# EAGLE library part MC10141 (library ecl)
Four Bit Universal Shift Register
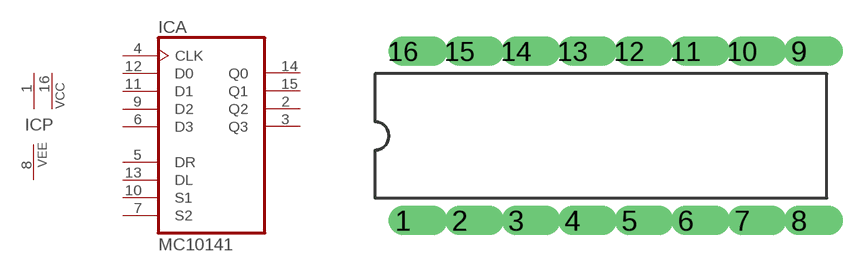
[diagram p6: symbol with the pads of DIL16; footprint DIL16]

Designator prefix IC; gates A=MC10141 P=2VCC1VEE

## MC10141  [DIL16]
1  P:VCC  pwr
2  A:Q2  out
3  A:Q3  out
4  A:CLK  in
5  A:DR  in
6  A:D3  in
7  A:S2  in
8  P:VEE  pwr
9  A:D2  in
10  A:S1  in
11  A:D1  in
12  A:D0  in
13  A:DL  in
14  A:Q0  out
15  A:Q1  out
16  P:VCC  pwr

## Footprint DIL16 (pad centres in mm)
drill 0.813 offset: 1 -8.89,-3.81; 2 -6.35,-3.81; 3 -3.81,-3.81; 4 -1.27,-3.81; 5 1.27,-3.81; 6 3.81,-3.81; 7 6.35,-3.81; 8 8.89,-3.81; 9 8.89,3.81; 10 6.35,3.81; 11 3.81,3.81; 12 1.27,3.81; 13 -1.27,3.81; 14 -3.81,3.81; 15 -6.35,3.81; 16 -8.89,3.81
